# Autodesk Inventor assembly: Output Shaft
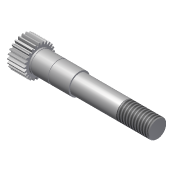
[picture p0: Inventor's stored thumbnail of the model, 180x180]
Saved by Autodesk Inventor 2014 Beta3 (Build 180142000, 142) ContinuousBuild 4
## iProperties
Created: 2011-01
Part Number: Output Shaft
Document SubType Name: Assembly
Designer: Beta-8540w
ClientObjectVersion: 1
Author: Beta-8540w
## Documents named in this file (2)
- C:\Inventor 2014 Essentials\Assemblies\Chapter 09\Design Accelerators\Shaft c09-02.iam
- C:\Inventor 2014 Essentials\Assemblies\Chapter 09\Design Accelerators\Shaft c09-02.ipt
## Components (1 placed, 1 different names)
1. Output Shaft:1
